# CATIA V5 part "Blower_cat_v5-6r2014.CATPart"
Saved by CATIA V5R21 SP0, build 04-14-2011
Part number: Blower
Bounding box of the stored display mesh (mm): x -139.7 to 139.7, y -139.7 to 139.7, z -63.5 to 184.15
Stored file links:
  D:\CATIA V5R21 E-RESOURCES\CATIA-V5R21\catia-v5r21-Tut\c12-catia-v5r21-tut\c12-catia-v5r21-tut01\Blower_cat_v5r21.CATPart
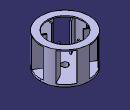
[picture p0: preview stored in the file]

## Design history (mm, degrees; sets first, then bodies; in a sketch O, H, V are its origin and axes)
Body1 (main body)
  Sketch1 on xy-plane, origin (0, 0, 0), H (1, 0, 0), V (0, 1, 0)
    circle A1 centre (0, 0) radius 139.7
    point P1 (0, 0)
    radius A1 = 139.7
    coincidence: P1 H, P1 O
  Pad1: profile Sketch1, direction (0, 0, 1), length 12.7
  Sketch2 on face of Pad1, origin (0, 0, 12.7), H (1, 0, 0), V (0, 1, 0)
    line L1 (0, 139.7) -> (0, 76.708)
    point P1 (0, 139.7)
    projected arc E1 centre (0, 0) radius 139.7 from (57.581, 127.2812) to (0, 139.7) ccw from edge of Pad1
    line L2 (6.35, 135.7416) -> (6.35, 76.708)
    arc A1 centre (0, 0) radius 135.89 from (55.7565, 123.9246) to (6.35, 135.7416) ccw
    line L3 (0, 76.708) -> (6.35, 76.708)
    line L4 (55.7565, 123.9246) -> (57.581, 127.2812)
    point P4 (55.7565, 123.9246)
    point P6 (6.35, 135.7416)
    length L1 = 62.992
    distance L1 L2 = 6.35
    distance E1 A1 = 3.81
    distance P6 P4 = 50.8
    coincidence: P1 V
    vertical: L1 V
    concentricity: E1 A1
    horizontal: L3 H
  Pad2: profile Sketch2, direction (0, 0, 1), length 165.1
  CircPattern1: of Pad2, instances 6, angular step 60, axis from edge of Sketch6
  Sketch3 on face of Pad1, origin (0, 0, 0), H (1, 0, 0), V (0, -1, 0)
    circle A1 centre (0, 0) radius 38.1
    radius A1 = 38.1
  Pad3: profile Sketch3, direction (0, 0, -1), length 63.5
  Sketch4 on face of Pad2, origin (0, 0, 177.8), H (1, 0, 0), V (0, 1, 0)
    circle A1 centre (0, 0) radius 139.7
    radius A1 = 139.7
  Pad4: profile Sketch4, direction (0, 0, 1), length 6.35
  Sketch5 on face of Pad4, origin (0, 0, 184.15), H (1, 0, 0), V (0, 1, 0)
    circle A1 centre (0, 0) radius 101.6
    circle A2 centre (0, 0) radius 19.05
    radius A2 = 19.05
    radius A1 = 101.6
  MultiPocket1: profile Sketch5, domains (length 381; length 6.35)
  Sketch6 on yz-plane, origin (0, 0, 0), H (0, 1, 0), V (0, 0, 1)
    line L1 (0, 3.7002) -> (0, 148.5199)
    point P1 (0, 3.7002)
    coincidence: P1 V
    vertical: L1 V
